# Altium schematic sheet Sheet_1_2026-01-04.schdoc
size 308 x 360 mm
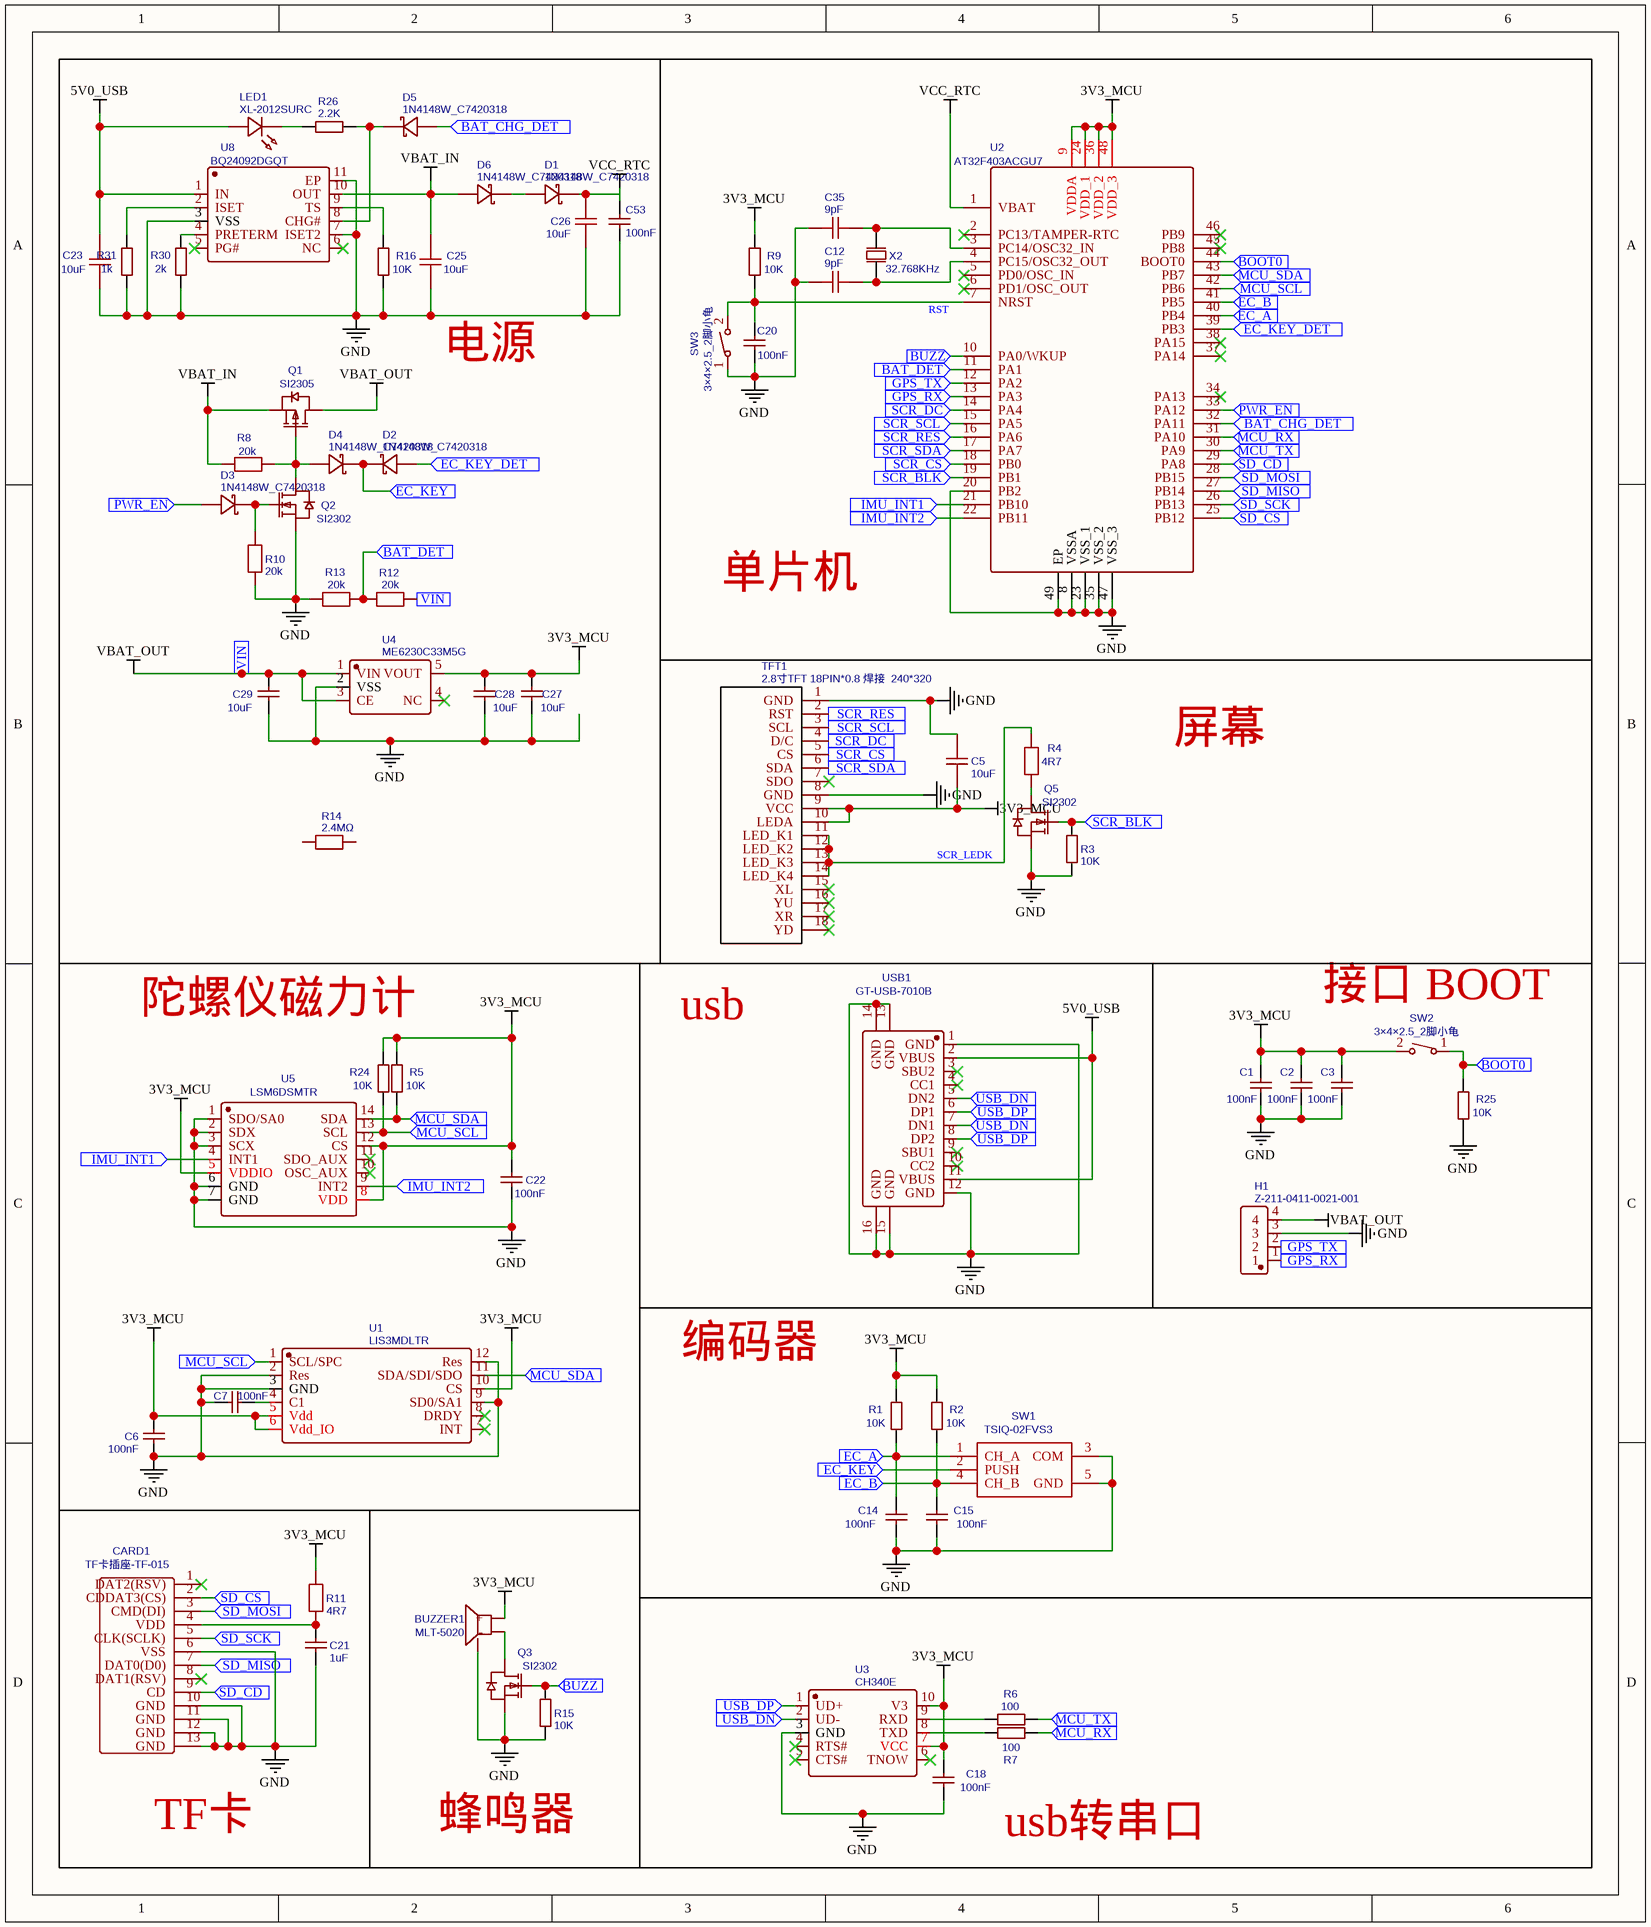
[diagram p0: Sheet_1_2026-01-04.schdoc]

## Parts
BUZZER1  MLT-5020  [BUZ-SMD_3P-L5.2-W5.2-P3.50-BR]
C1  100nF  [C0805]
C2  100nF  [C0805]
C3  100nF  [C0805]
C5  10uF  [C0805]
C6  100nF  [C0805]
C7  100nF  [C0805]
C12  9pF  [C0805]
C14  100nF  [C0805]
C15  100nF  [C0805]
C18  100nF  [C0805]
C20  100nF  [C0805]
C21  1uF  [C0805]
C22  100nF  [C0805]
C23  10uF  [C0805]
C25  10uF  [C0805]
C26  10uF  [C0805]
C27  10uF  [C0805]
C28  10uF  [C0805]
C29  10uF  [C0805]
C35  9pF  [C0805]
C53  100nF  [C0805]
CARD1  TF卡插座-TF-015  [TF卡插座-TF-015]
D1  1N4148W_C7420318  [SOD-123_L2.7-W1.6-LS3.7-FD]
D2  1N4148W_C7420318  [SOD-123_L2.7-W1.6-LS3.7-FD]
D3  1N4148W_C7420318  [SOD-123_L2.7-W1.6-LS3.7-FD]
D4  1N4148W_C7420318  [SOD-123_L2.7-W1.6-LS3.7-FD]
D5  1N4148W_C7420318  [SOD-123_L2.7-W1.6-LS3.7-FD]
D6  1N4148W_C7420318  [SOD-123_L2.7-W1.6-LS3.7-FD]
H1  Z-211-0411-0021-001  [HDR-TH_4P-P2.54-V-M]
LED1  XL-2012SURC  [LED0805-RD_RED]
Q1  SI2305  [SOT-23-3_L2.9-W1.3-P1.90-LS2.4-BR]
Q2  SI2302  [SOT-23-3_L2.9-W1.3-P1.90-LS2.4-BR]
Q3  SI2302  [SOT-23-3_L2.9-W1.3-P1.90-LS2.4-BR]
Q5  SI2302  [SOT-23-3_L2.9-W1.3-P1.90-LS2.4-BR]
R1  10K  [R0805]
R2  10K  [R0805]
R3  10K  [R0805]
R4  4R7  [R0805]
R5  10K  [R0805]
R6  100  [R0805]
R7  100  [R0805]
R8  20k  [R0805]
R9  10K  [R0805]
R10  20k  [R0805]
R11  4R7  [R0805]
R12  20k  [R0805]
R13  20k  [R0805]
R14  2.4MΩ  [R0603]
R15  10K  [R0805]
R16  10K  [R0805]
R24  10K  [R0805]
R25  10K  [R0805]
R26  2.2K  [R0805]
R30  2k  [R0805]
R31  1k  [R0805]
SW1  TSIQ-02FVS3  [贴片旋转编码开关_TSIQ-02FVS3]
SW2  3×4×2.5_2脚小龟  [SW-SMD_L4.0-W2.9-LS5.0]
SW3  3×4×2.5_2脚小龟  [SW-SMD_L4.0-W2.9-LS5.0]
TFT1  2.8寸TFT 18PIN*0.8 焊接  240*320  [2.8寸TFT SPI,18PIN 0.8MM 240*320]
U1  LIS3MDLTR  [LGA-12_L2.0-W2.0-P0.50-BL]
U2  AT32F403ACGU7  [QFN-48_L6.0-W6.0-P0.40-BL-EP4.2]
U3  CH340E  [MSOP-10_L3.0-W3.0-P0.50-LS5.0-BL]
U4  ME6230C33M5G  [TSOT-23-5_L2.9-W1.6-P0.95-LS2.8-BR]
U5  LSM6DSMTR  [LGA-14_L3.0-W2.5-P0.50-TL]
U8  BQ24092DGQT  [HVSSOP-10_L3.0-W3.0-P0.50-LS4.9-BL-EP]
USB1  GT-USB-7010B  [USB-C-SMD_GT-USB-7010B]
X2  32.768KHz  [OSC-SMD_2P-L3.2-W1.5]

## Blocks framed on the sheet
电源: C23 C25-C29 C53 D1-D6 LED1 Q1 Q2 R8 R10 R12-R14 R16 R26 R30 R31 U4 U8
单片机: C12 C20 C35 R9 SW3 U2 X2
屏幕: C5 Q5 R3 R4 TFT1
陀螺仪磁力计: C6 C7 C22 R5 R24 U1 U5
usb: USB1
接口 BOOT: C1-C3 H1 R25 SW2
编码器: C14 C15 R1 R2 SW1
TF卡: C21 CARD1 R11
蜂鸣器: BUZZER1 Q3 R15
usb转串口: C18 R6 R7 U3

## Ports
BAT_CHG_DET (in), BAT_DET (in), BOOT0 (in), BUZZ (in), EC_A (in), EC_B (in), EC_KEY (in), EC_KEY_DET (in), GPS_RX (in), GPS_TX (in), IMU_INT1 (in), IMU_INT2 (in), MCU_RX (in), MCU_SCL (in), MCU_SDA (in), MCU_TX (in), PWR_EN (in), SCR_BLK (in), SCR_CS (in), SCR_DC (in), SCR_RES (in), SCR_SCL (in), SCR_SDA (in), SD_CD (in), SD_CS (in), SD_MISO (in), SD_MOSI (in), SD_SCK (in), USB_DN (in), USB_DP (in), VIN (in)

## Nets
3V3_MCU: BUZZER1.2(+) C1.2 C2.2 C3.2 C5.1 C6.1 C18.1 C22.1 C27.1 C28.1 R1.2 R2.1 R5.1 R9.1 R11.1 R24.1 SW2.2 TFT1.9(VCC) TFT1.10(LEDA) U1.5(Vdd) U1.6(Vdd_IO) U1.10(CS) U2.9(VDDA) U2.24(VDD_1) U2.36(VDD_2) U2.48(VDD_3) U3.7(VCC) U3.10(V3) U4.5(VOUT) U5.5(VDDIO) U5.8(VDD) U5.12(CS)
5V0_USB: C23.2 LED1.2(A) U8.1(IN) USB1.2(VBUS) USB1.11(VBUS)
GND: BUZZER1.1(NC) C1.1 C2.1 C3.1 C5.2 C6.2 C7.2 C12.1 C14.1 C15.1 C18.2 C20.2 C21.2 C22.2 C23.1 C25.1 C26.1 C27.2 C28.2 C29.2 C35.1 C53.2 CARD1.6(VSS) CARD1.10(GND) CARD1.11(GND) CARD1.12(GND) CARD1.13(GND) H1.3 Q2.2(S) Q3.2(S) Q5.2(S) R3.2 R10.1 R13.1 R15.1 R16.2 R25.2 R30.1 R31.1 SW1.3(COM) SW1.5(GND) SW3.1 TFT1.1(GND) TFT1.8(GND) U1.2(Res) U1.3(GND) U1.9(SD0/SA1) U1.12(Res) U2.8(VSSA) U2.20(PB2) U2.23(VSS_1) U2.35(VSS_2) U2.47(VSS_3) U2.49(EP) U3.3(GND) U4.2(VSS) U5.1(SDO/SA0) U5.2(SDX) U5.3(SCX) U5.6(GND) U5.7(GND) U8.3(VSS) U8.7(ISET2) U8.11(EP) USB1.1(GND) USB1.12(GND) USB1.13(GND) USB1.14(GND) USB1.15(GND) USB1.16(GND)
VBAT_IN: C25.2 D6.1(A) Q1.2(S) R8.1 U8.10(OUT)
VBAT_OUT: C29.1 H1.4 Q1.3(D) R12.2 U4.1(VIN) U4.3(CE) ; port VIN
VCC_RTC: C26.2 C53.1 D1.2(K) U2.1(VBAT)
BAT_CHG_DET: D5.1(A) U2.32(PA11) ; port BAT_CHG_DET
BAT_DET: R12.1 R13.2 U2.11(PA1) ; port BAT_DET
BOOT0: R25.1 SW2.1 U2.44(BOOT0) ; port BOOT0
BUZZ: Q3.1(G) R15.2 U2.10(PA0/WKUP) ; port BUZZ
EC_A: C14.2 R1.1 SW1.1(CH_A) U2.40(PB4) ; port EC_A
EC_B: C15.2 R2.2 SW1.4(CH_B) U2.41(PB5) ; port EC_B
EC_KEY: D2.2(K) D4.2(K) SW1.2(PUSH) ; port EC_KEY
EC_KEY_DET: D2.1(A) U2.39(PB3) ; port EC_KEY_DET
GPS_RX: H1.1 U2.13(PA3) ; port GPS_RX
GPS_TX: H1.2 U2.12(PA2) ; port GPS_TX
IMU_INT1: U2.21(PB10) U5.4(INT1) ; port IMU_INT1
IMU_INT2: U2.22(PB11) U5.9(INT2) ; port IMU_INT2
MCU_RX: R7.1 U2.31(PA10) ; port MCU_RX
MCU_SCL: R24.2 U1.1(SCL/SPC) U2.42(PB6) U5.13(SCL) ; port MCU_SCL
MCU_SDA: R5.2 U1.11(SDA/SDI/SDO) U2.43(PB7) U5.14(SDA) ; port MCU_SDA
MCU_TX: R6.2 U2.30(PA9) ; port MCU_TX
PWR_EN: D3.1(A) U2.33(PA12) ; port PWR_EN
RST: C20.1 R9.2 SW3.2 U2.7(NRST)
SCR_BLK: Q5.1(G) R3.1 U2.19(PB1) ; port SCR_BLK
SCR_CS: TFT1.5(CS) U2.18(PB0) ; port SCR_CS
SCR_DC: TFT1.4(D/C) U2.14(PA4) ; port SCR_DC
SCR_LEDK: R4.1 TFT1.11(LED_K1) TFT1.12(LED_K2) TFT1.13(LED_K3) TFT1.14(LED_K4)
SCR_RES: TFT1.2(RST) U2.16(PA6) ; port SCR_RES
SCR_SCL: TFT1.3(SCL) U2.15(PA5) ; port SCR_SCL
SCR_SDA: TFT1.6(SDA) U2.17(PA7) ; port SCR_SDA
SD_CD: CARD1.9(CD) U2.29(PA8) ; port SD_CD
SD_CS: CARD1.2(CDDAT3(CS)) U2.25(PB12) ; port SD_CS
SD_MISO: CARD1.7(DAT0(D0)) U2.27(PB14) ; port SD_MISO
SD_MOSI: CARD1.3(CMD(DI)) U2.28(PB15) ; port SD_MOSI
SD_SCK: CARD1.5(CLK(SCLK)) U2.26(PB13) ; port SD_SCK
USB_DN: U3.2(UD-) USB1.5(DN2) USB1.7(DN1) ; port USB_DN
USB_DP: U3.1(UD+) USB1.6(DP1) USB1.8(DP2) ; port USB_DP
NetBUZZER1_3: BUZZER1.3(-) Q3.3(D)
NetC7_1: C7.1 U1.4(C1)
NetC12_2: C12.2 U2.4(PC15/OSC32_OUT) X2.2(OSC2)
NetC21_1: C21.1 CARD1.4(VDD) R11.2
NetC35_2: C35.2 U2.3(PC14/OSC32_IN) X2.1(OSC1)
NetD1_1: D1.1(A) D6.2(K)
NetD3_2: D3.2(K) Q2.1(G) R10.2
NetD4_1: D4.1(A) Q1.1(G) Q2.3(D) R8.2
NetD5_2: D5.2(K) R26.2 U8.8(CHG#)
NetLED1_1: LED1.1(K) R26.1
NetQ5_3: Q5.3(D) R4.2
NetR6_1: R6.1 U3.9(RXD)
NetR7_2: R7.2 U3.8(TXD)
NetR16_1: R16.1 U8.9(TS)
NetR30_2: R30.2 U8.4(PRETERM)
NetR31_2: R31.2 U8.2(ISET)

Not connected (* = marked no-connect by the designer): CARD1 1(DAT2(RSV))* 8(DAT1(RSV))*; R14 1 2; TFT1 7(SDO)* 15(XL)* 16(YU)* 17(XR)* 18(YD)*; U1 7(INT)* 8(DRDY)*; U2 2(PC13/TAMPER-RTC)* 5(PD0/OSC_IN)* 6(PD1/OSC_OUT)* 34(PA13)* 37(PA14)* 38(PA15)* 45(PB8)* 46(PB9)*; U3 4(RTS#)* 5(CTS#)* 6(TNOW)*; U4 4(NC)*; U5 10(OSC_AUX)* 11(SDO_AUX)*; U8 5(PG#)* 6(NC)*; USB1 3(SBU2)* 4(CC1)* 9(SBU1)* 10(CC2)*

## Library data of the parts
BUZZER1 = MLT-5020: Manufacturer: HNDZ
C1-C3 C6 C7 C14 C15 C18 C20 C22 = 100nF: Manufacturer Part: CL05B104KO5NNNC; Manufacturer: SAMSUNG; nameAlias: Capacitance
C5 C26 = 10uF: nameAlias: Value(F); Contributor: LCEDA_Lib
C12 C35 = 9pF: Manufacturer: Guangdong Fenghua Advanced Tech; Manufacturer Part: 0402CG9R0D500NT; nameAlias: Capacitance; Contributor: LCSC
C21 = 1uF: nameAlias: Capacitance
C23 C25 = 10uF: Manufacturer: SANYEAR; Manufacturer Part: C0603X5R106M160NT; nameAlias: Capacitance; Contributor: LCSC
C27-C29 = 10uF: nameAlias: Capacitance
C53 = 100nF: nameAlias: Capacitance
CARD1 = TF卡插座-TF-015: Manufacturer: SOFNG; Manufacturer Part: TF-015; Contributor: DoM
D1-D6 = 1N4148W_C7420318: Manufacturer: 宏迦橙; Contributor: lcsc
H1 = Z-211-0411-0021-001: Manufacturer: Nextron(正凌); Manufacturer Part: Z-21104110021001; Contributor: LCSC
LED1 = XL-2012SURC: Manufacturer: XINGLIGHT(成兴光); Contributor: LCSC
Q1 = SI2305: Contributor: LCSC
Q2 Q3 Q5 = SI2302: Contributor: LCSC
R1-R3 R5 R9 R15 R16 R24 R25 = 10K: Manufacturer: UniOhm; Manufacturer Part: 0402WGF1002TCE; nameAlias: Resistance (Ohms)
R4 R11 = 4R7: Manufacturer: UNI-ROYAL(Uniroyal Elec); Manufacturer Part: CQ03WAF470KT5E; Contributor: LCSC
R6 R7 = 100: Manufacturer: UniOhm; Manufacturer Part: 0402WGF1000TCE; nameAlias: Resistance (Ohms)
R8 R10 R12 R13 = 20k: Manufacturer: UNI-ROYAL(Uniroyal Elec); Manufacturer Part: NQ02WGJ0203TCE; Contributor: LCSC
R14 = 2.4MΩ: Manufacturer: LIZ(丽智电子); Manufacturer Part: CR0603FA2404G; nameAlias: Value; Contributor: lcsc
R26 = 2.2K: Manufacturer: UniOhm; Manufacturer Part: 0402WGF3301TCE; nameAlias: Resistance (Ohms)
R30 = 2k: nameAlias: Resistance (Ohms)
R31 = 1k: nameAlias: Resistance (Ohms)
SW1 = TSIQ-02FVS3: Contributor: 222465.255411
SW2 SW3 = 3×4×2.5_2脚小龟: Manufacturer: XKB Enterprise; Manufacturer Part: TS-1185-C-B-B-A; Contributor: LCSC
TFT1 = 2.8寸TFT 18PIN*0.8 焊接  240*320: Contributor: tangj
U1 = LIS3MDLTR: Manufacturer: STMicroelectronics; Contributor: LCSC
U2 = AT32F403ACGU7: Manufacturer: ARTERY(雅特力); Contributor: DoM
U3 = CH340E: Manufacturer: WCH
U4 = ME6230C33M5G: Manufacturer: MICRONE(南京微盟); Contributor: LCSC
U5 = LSM6DSMTR: Manufacturer: STMicroelectronics
U8 = BQ24092DGQT: Manufacturer: TI(德州仪器); Contributor: LCSC
USB1 = GT-USB-7010B: Manufacturer: G-Switch(品赞); Contributor: LCSC
X2 = 32.768KHz: Manufacturer: JGHC; Manufacturer Part: S3132768092070; nameAlias: Frequency; Contributor: LCSC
